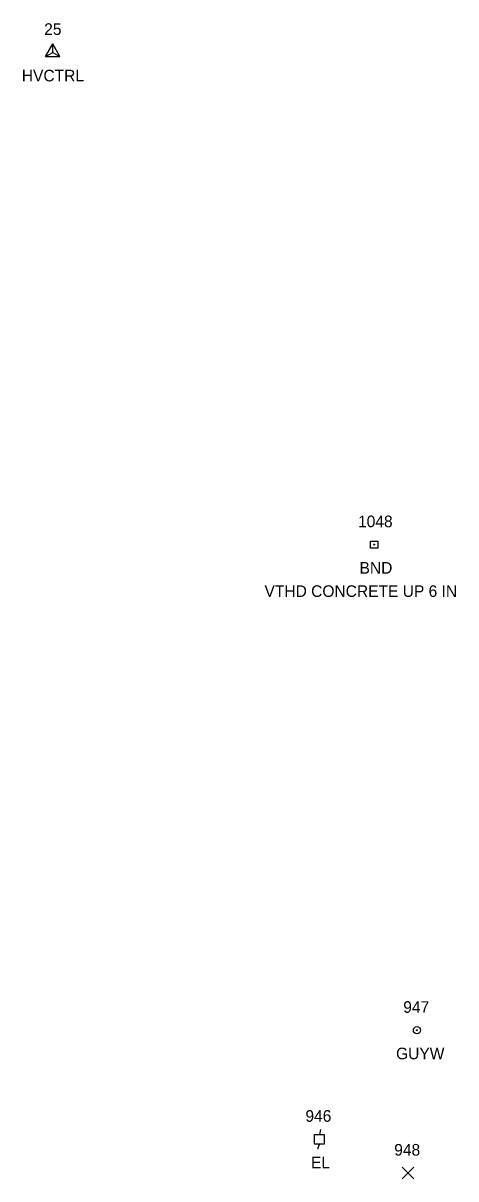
# Model space of a CAD drawing. Extents: x 1764889 to 1767296, y 695936 to 698960.
# Drawn here: x 1766167.3 to 1766241.8, y 696517.4 to 696716.3 of the extents above; entities that cross this region are included whole.
import ezdxf

# ---------------------------------------------------------------- set-up
doc = ezdxf.new("R2010")
doc.units = 0
for name, color, linetype in [('C_A', 7, 'Continuous'), ('C_I', 7, 'Continuous'), ('CPSM', 7, 'Continuous'), ('L_I', 7, 'Continuous'), ('L_TIC', 7, 'Continuous'), ('Level 18', 7, 'Continuous'), ('M_A', 7, 'Continuous'), ('M_C', 7, 'Continuous'), ('M_I', 7, 'Continuous'), ('U_A', 7, 'Continuous'), ('U_I', 7, 'Continuous'), ('UEPT', 7, 'Continuous'), ('UPGW', 7, 'Continuous')]:
    doc.layers.add(name, color=color, linetype=linetype)

msp = doc.modelspace()

# ---------------------------------------------------------------- linework, layer by layer
at = {"layer": 'CPSM'}
for p, q in [((1766171.16, 696710.53), (1766172.41, 696712.7)), ((1766171.16, 696710.53), (1766172.41, 696711.25)), ((1766173.66, 696710.53), (1766172.41, 696712.7)), ((1766172.41, 696711.25), (1766172.41, 696712.7)), ((1766172.41, 696711.25), (1766172.41, 696711.25)), ((1766172.41, 696711.25), (1766173.66, 696710.53)), ((1766171.16, 696710.53), (1766173.66, 696710.53))]:
    msp.add_line(p, q, dxfattribs=at)
at = {"layer": 'L_TIC'}
for points in [[(1766232.53, 696517.36), (1766234.53, 696519.36)], [(1766234.53, 696517.36), (1766232.53, 696519.36)]]:
    msp.add_lwpolyline(points, dxfattribs=at)
at = {"layer": 'Level 18'}
msp.add_lwpolyline([(1766227.09, 696627.14), (1766228.34, 696627.14), (1766228.34, 696625.89), (1766227.09, 696625.89)], close=True, dxfattribs=at)
msp.add_circle((1766227.71, 696626.52), 0.0833, dxfattribs=at)
at = {"layer": 'UEPT'}
for p, q in [((1766218.47, 696525.85), (1766218.3, 696525.02)), ((1766217.47, 696523.35), (1766217.47, 696525.02)), ((1766217.47, 696525.02), (1766219.14, 696525.02)), ((1766218.3, 696524.19), (1766218.3, 696524.19)), ((1766219.14, 696525.02), (1766219.14, 696523.35)), ((1766219.14, 696523.35), (1766217.47, 696523.35)), ((1766218.05, 696522.52), (1766218.3, 696523.35))]:
    msp.add_line(p, q, dxfattribs=at)
at = {"layer": 'UPGW'}
for radius in [0.625, 0.0833]:
    msp.add_circle((1766235.08, 696542.94), radius, dxfattribs=at)

# ---------------------------------------------------------------- texts
at = {"layer": 'C_A'}
msp.add_text('HVCTRL', height=2, dxfattribs=at).set_placement((1766167.1, 696706.25))
at = {"layer": 'C_I'}
msp.add_text('25', height=2, dxfattribs=at).set_placement((1766170.95, 696714.25))
at = {"layer": 'L_I'}
msp.add_text('948', height=2, dxfattribs=at).set_placement((1766231.17, 696521.36))
at = {"layer": 'M_A'}
msp.add_text('BND', height=2, dxfattribs=at).set_placement((1766225.2, 696621.52))
at = {"layer": 'M_C'}
msp.add_text('VTHD CONCRETE UP 6 IN', height=2, dxfattribs=at).set_placement((1766208.85, 696617.52))
at = {"layer": 'M_I'}
msp.add_text('1048', height=2, dxfattribs=at).set_placement((1766224.94, 696629.52))
at = {"layer": 'U_A'}
for s, p in [('GUYW', (1766231.48, 696537.94)), ('EL', (1766216.84, 696519.19))]:
    msp.add_text(s, height=2, dxfattribs=at).set_placement(p)
at = {"layer": 'U_I'}
for s, p in [('947', (1766232.72, 696545.94)), ('946', (1766215.89, 696527.19))]:
    msp.add_text(s, height=2, dxfattribs=at).set_placement(p)

doc.saveas('drawing.dxf')
